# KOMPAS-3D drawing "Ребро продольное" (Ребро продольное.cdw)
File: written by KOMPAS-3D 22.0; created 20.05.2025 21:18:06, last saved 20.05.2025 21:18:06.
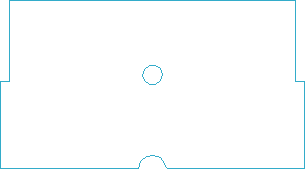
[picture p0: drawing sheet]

Sheet 1: A4, portrait

Document properties: Автор: user; Масса: 0.575358; Полное имя файла: Ребро продольное.m3d

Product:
- Part/product: Ребро продольное
    Масса: 0.575358
- Part/product: Ребро продольное  | designation 01
    Масса: 0.542298

Title block, sheet 1: Наименование: Ребро продольное; Материал: Сталь 10 ГОСТ 1050-2013; Масса: 0,58; Количество листов документа: 1; Форматы листов документа: A4

Views: Вид 1, Слева
Referenced files in D:\Работа\2025\5. Май\Задание №6 - Тележка для крыши\3Д\Тележка в сборе\Корпус тележки\: Ребро продольное.m3d
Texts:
  Без оформления
Dimensions and other numbers on the sheet: 1:1; 1; 0,58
